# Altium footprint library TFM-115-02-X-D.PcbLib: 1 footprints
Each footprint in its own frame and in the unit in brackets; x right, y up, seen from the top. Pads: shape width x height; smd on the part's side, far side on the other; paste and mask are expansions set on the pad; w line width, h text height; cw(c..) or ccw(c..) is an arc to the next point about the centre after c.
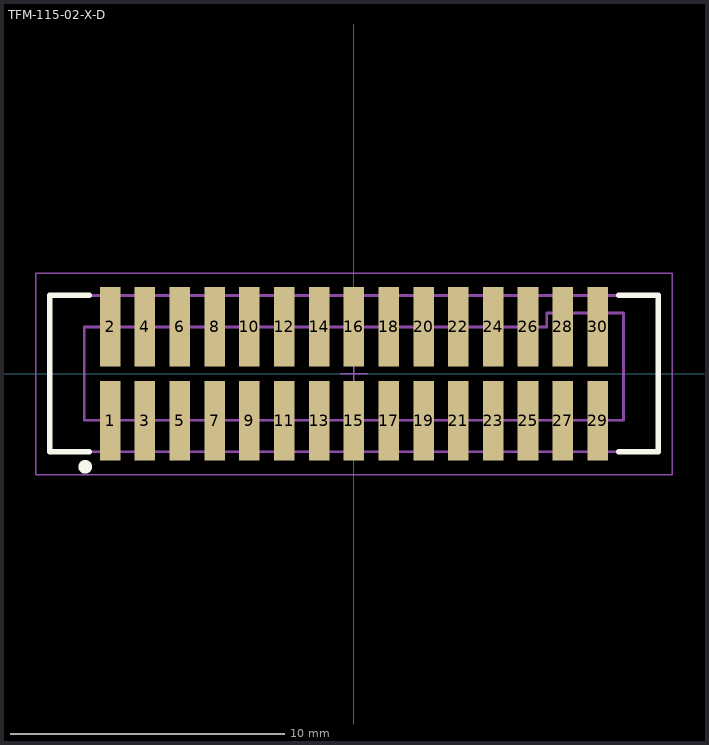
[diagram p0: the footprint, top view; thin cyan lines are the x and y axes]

## TFM-115-02-X-D [mm] "1.27mm pitch, 30 pin, terminal strip; SMT"
height 5.59
pads (30):
  rect 0.75x2.9 smd mask+0: 1(-8.89,-1.714) 2(-8.89,1.714) 3(-7.62,-1.714) 4(-7.62,1.714) 5(-6.35,-1.714) 6(-6.35,1.714) 7(-5.08,-1.714) 8(-5.08,1.714) 9(-3.81,-1.714) 10(-3.81,1.714) 11(-2.54,-1.714) 12(-2.54,1.714) 13(-1.27,-1.714) 14(-1.27,1.714) 15(0,-1.714) 16(0,1.714) 17(1.27,-1.714) 18(1.27,1.714) 19(2.54,-1.714) 20(2.54,1.714) 21(3.81,-1.714) 22(3.81,1.714) 23(5.08,-1.714) 24(5.08,1.714) 25(6.35,-1.714) 26(6.35,1.714) 27(7.62,-1.714) 28(7.62,1.714) 29(8.89,-1.714) 30(8.89,1.714)
Top Overlay:
  circle w0.25: c-9.8,-3.4 r0.125
  lines w0.2: -9.65,-2.85 -11.1,-2.85 -11.1,2.85 -9.65,2.85 ; 9.65,-2.85 11.1,-2.85 11.1,2.85 9.65,2.85
Mechanical 12:
  lines w0.001: -11.1,-2.85 -11.1,2.85 11.1,2.85 11.1,-2.85 -11.1,-2.85 ; -9.83,-1.702 -9.83,1.702 7.036,1.702 7.036,2.21 9.83,2.21 9.83,-1.702 -9.83,-1.702
Mechanical 13:
  lines w0.1: -11.1,-2.85 -11.1,2.85 11.1,2.85 11.1,-2.85 -11.1,-2.85 ; -9.83,-1.702 -9.83,1.702 7.036,1.702 7.036,2.21 9.83,2.21 9.83,-1.702 -9.83,-1.702
  text ".Designator" at 0,-0.127 h1.52
Mechanical 15:
  lines w0.05: -0.5,0 0.5,0 ; 0,-0.5 0,0.5 ; -11.6,-3.683 -11.6,3.65 11.608,3.65 11.608,-3.683 -11.6,-3.683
